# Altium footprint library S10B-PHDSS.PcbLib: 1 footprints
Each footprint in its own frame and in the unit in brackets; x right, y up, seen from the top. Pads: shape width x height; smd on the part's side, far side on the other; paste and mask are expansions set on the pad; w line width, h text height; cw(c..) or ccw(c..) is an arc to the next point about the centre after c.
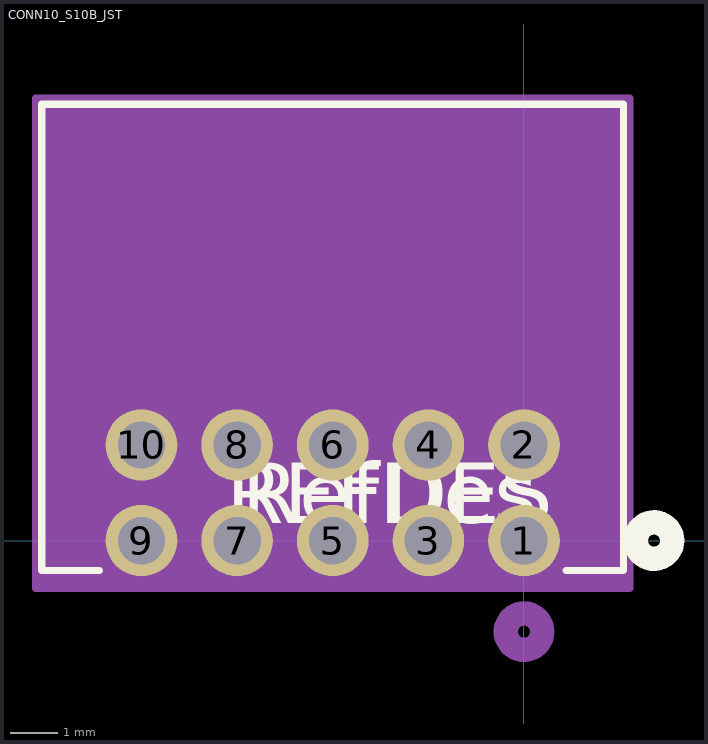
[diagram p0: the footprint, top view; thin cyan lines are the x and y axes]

## CONN10_S10B_JST [mil]
pads (10):
  round 59 / inner round 60 / far side round 59 hole 39 paste-29.5 mask+0: 1(0,0) 2(0,78.74) 3(-78.74,0) 4(-78.74,78.74) 5(-157.48,0) 6(-157.48,78.74) 7(-236.22,0) 8(-236.22,78.74) 9(-314.96,0) 10(-314.96,78.74)
Top Overlay:
  circle w20: c107.02,0 r15
  lines w6: -349.69,-24.67 -396.98,-24.67 -396.98,359.33 82.02,359.33 82.02,-24.67 34.73,-24.67
  text "RefDes" at -232.48,14.37 h50
  text "REFDES" at -244.98,14.37 h50
Bottom Overlay:
  circle w20: c107.02,0 r15
Mechanical 13:
  circle w20: c0,-75 r15
  lines w1: -391.98,-19.67 77.02,-19.67 77.02,354.33 -391.98,354.33 -391.98,-19.67
  text "RefDes2" at -244.98,14.37 h50
Mechanical 15:
  region: 87.02,364.33 -401.98,364.33 -401.98,-39.5 87.02,-39.5
  lines w6: -401.98,-39.5 -401.98,364.33 87.02,364.33 87.02,-39.5 -401.98,-39.5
